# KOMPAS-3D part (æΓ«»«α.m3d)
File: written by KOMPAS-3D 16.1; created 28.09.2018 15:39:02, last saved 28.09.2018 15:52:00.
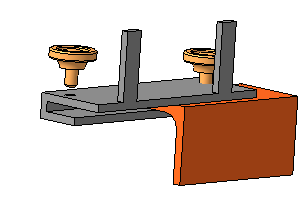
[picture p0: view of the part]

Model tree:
1. Эскиз:1
2. Операция выдавливания:1
     Расстояние 1 = 140
3. Эскиз:2
4. Вырезать элемент выдавливания:1
     Расстояние 1 = 45
5. Эскиз:3
6. Вырезать элемент выдавливания:2
     Расстояние 1 = 5
7. Условное изображение резьбы:1  (labels: M8)
     Длина резьбы = 5; Шаг резьбы = 1.25; Номинальный диаметр резьбы = 8
8. Подгонка:1
9. Зеркальный массив:1
10. Экземпляр ( 1 )
11. Экземпляр ( 2 )  (with: Вырезать элемент выдавливания:2)
12. Эскиз:4
13. Операция выдавливания:2
     Расстояние 1 = 100
14. Скругление:1  (labels: SYSTEM_PROPERTY_ADDITIONAL_FOR:5.000000; ГОСТ 21332-75)
     Радиус = 10

Referenced files in C:\Program Files\ASCON\KOMPAS-3D V16\Libs\PartLib\DATA\vault\Methods\Kompas\3D\Fastening_GOST\21331_37\: PLib_Screws_with_bead_GOST_21333_911.a3d
Referenced files in C:\Program Files\ASCON\KOMPAS-3D V16\Sys\Thread\: cil0_8724-2002 coarse.xml
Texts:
  Винт B2.М8x12 ГОСТ 21332-75
  Isp21332
  Isp21334
  Isp21337
  Isp21333
  Isp21336
  Isp21335
  (-) Винт B2.М8x12 ГОСТ 21332-75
